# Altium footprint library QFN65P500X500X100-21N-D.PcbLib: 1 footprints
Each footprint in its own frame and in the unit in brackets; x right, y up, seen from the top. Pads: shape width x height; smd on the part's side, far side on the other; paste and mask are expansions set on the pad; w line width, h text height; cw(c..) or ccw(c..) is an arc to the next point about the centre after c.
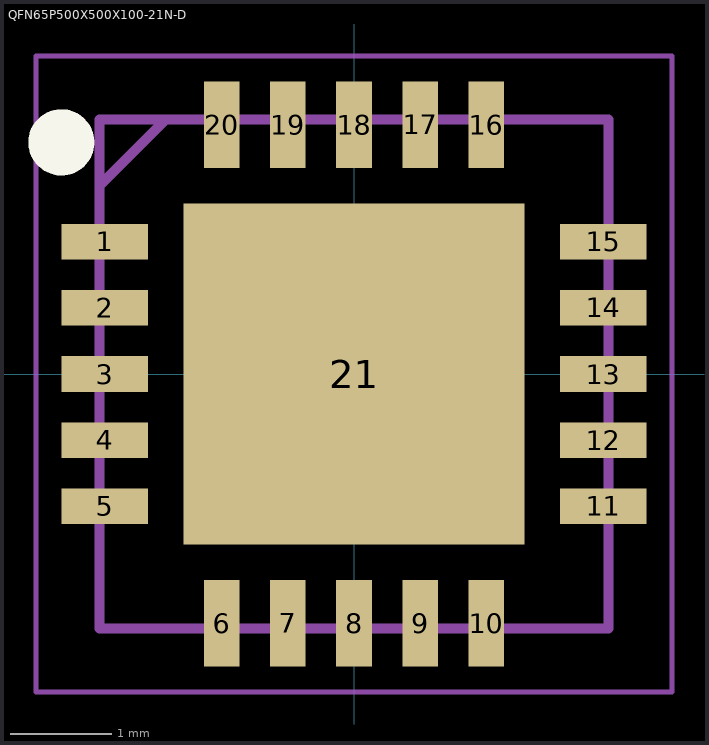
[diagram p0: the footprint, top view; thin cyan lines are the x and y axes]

## QFN65P500X500X100-21N-D [mm]
pads (21):
  rect 0.85x0.35 smd: 1(-2.45,1.3) 2(-2.45,0.65) 3(-2.45,0) 4(-2.45,-0.65) 5(-2.45,-1.3) 11(2.45,-1.3) 12(2.45,-0.65) 13(2.45,0) 14(2.45,0.65) 15(2.45,1.3)
  rect 0.35x0.85 smd: 6(-1.3,-2.45) 7(-0.65,-2.45) 8(0,-2.45) 9(0.65,-2.45) 10(1.3,-2.45) 16(1.3,2.45) 17(0.65,2.45) 18(0,2.45) 19(-0.65,2.45) 20(-1.3,2.45)
  rect 3.35x3.35 smd: 21(0,0)
Top Overlay:
  circle w0.325: c-2.875,2.275 r0.162
Mechanical 15:
  lines w0.1: -2.5,1.85 -1.85,2.5 ; -2.5,-2.5 2.5,-2.5 2.5,2.5 -2.5,2.5 -2.5,-2.5
Mechanical 20:
  lines w0.05: -3.125,-3.125 3.125,-3.125 3.125,3.125 -3.125,3.125 -3.125,-3.125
